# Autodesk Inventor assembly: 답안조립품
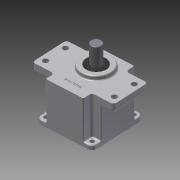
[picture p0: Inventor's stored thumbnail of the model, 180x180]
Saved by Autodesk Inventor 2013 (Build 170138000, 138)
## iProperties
Created: 2015-07
Part Number: 답안조립품
Document SubType Name: Assembly
Designer: user
Author: user
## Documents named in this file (12)
- C:\Users\user\Desktop\450734V1012\답안조립품.iam
- C:\Users\user\Desktop\450734V1012\메인축.ipt
- C:\Users\user\Desktop\450734V1012\베어링 6003.ipt
- 베어링 6003.ipt
- C:\Users\user\Desktop\450734V1012\베어링 608.ipt
- 베어링 608.ipt
- C:\Users\user\Desktop\450734V1012\서브축.ipt
- C:\Users\user\Desktop\450734V1012\본체.ipt
- C:\Users\user\Desktop\450734V1008\커버.ipt
- C:\Users\user\Desktop\450734V1012\오일실 8x22x7.ipt
- C:\Users\user\Desktop\450734V1012\오일실 17x32x8.ipt
- C:\Users\user\Desktop\450734V1012\M4x0.5x16.ipt
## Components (4 placed, 1 different names)
1. M4x0.5x12:1
2. M4x0.5x12:2
3. M4x0.5x12:3
4. M4x0.5x12:4
